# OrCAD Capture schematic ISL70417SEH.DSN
size A
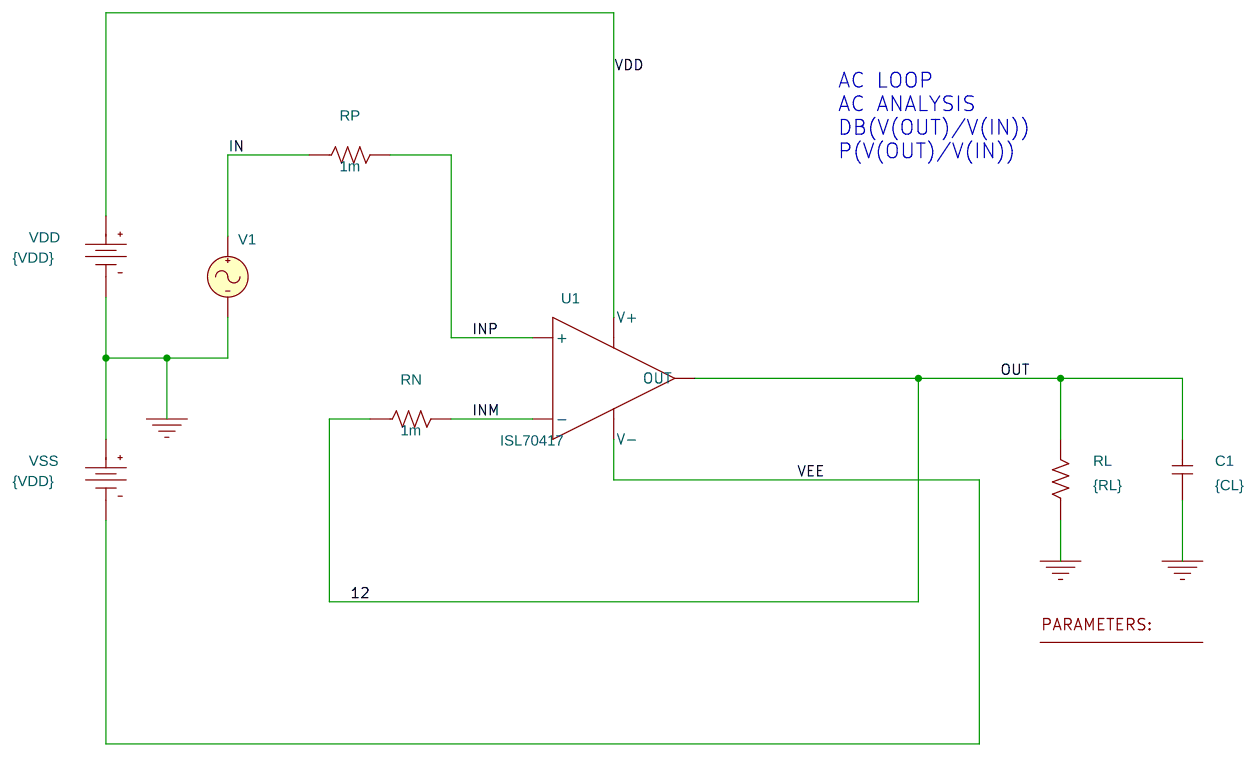
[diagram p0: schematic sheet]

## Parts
1  PARAM
C1  {CL}  [RAD/CK05]
RL  {RL}  [AX/RC05]
RN  1m  [AX/RC05]
RP  1m  [AX/RC05]
U1  ISL70417  [DIP.100/14/W.300/L.800]
V1  VAC
VDD  VDC
VSS  VDC

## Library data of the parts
1 = PARAM: CL: 10p; RF: 100k; RL: 10k; VDD: 15.0
C1 = C
RL RN RP = R
U1 = ISL70417
V1 = VAC
VDD VSS = VDC: DC: {VDD}

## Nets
VDD: U1.V+ VDD.0(+)
VEE: U1.V- VSS.1(-)
0: C1.1 RL.1 V1.2(-) VDD.1(-) VSS.0(+)
12: C1.2 RL.2 RN.1 U1.OUT
IN: RP.1 V1.1(+)
INM: RN.2 U1.-
INP: RP.2 U1.+

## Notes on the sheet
- AC LOOP
  AC ANALYSIS
  DB(V(OUT)/V(IN))
  P(V(OUT)/V(IN))
